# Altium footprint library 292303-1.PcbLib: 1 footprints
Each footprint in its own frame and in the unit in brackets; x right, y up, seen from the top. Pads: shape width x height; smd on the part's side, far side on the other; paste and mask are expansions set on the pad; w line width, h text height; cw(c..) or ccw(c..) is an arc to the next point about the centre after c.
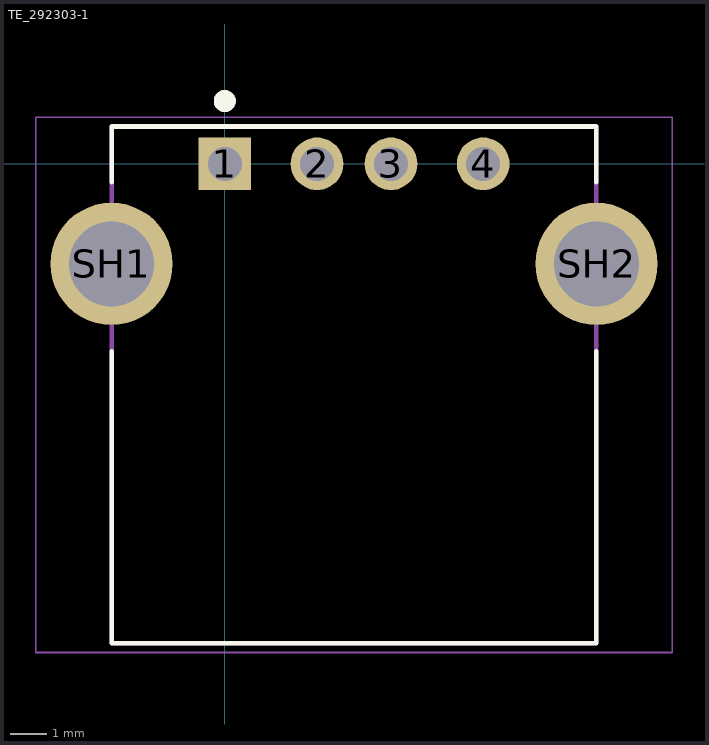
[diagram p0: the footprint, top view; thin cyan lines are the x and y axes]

## TE_292303-1 [mm]
pads (6):
  rect 1.428x1.428 hole 0.92: 1(0,0)
  round 1.428 hole 0.92: 2(2.5,0) 3(4.5,0) 4(7,0)
  round 3.316 hole 2.3: SH1(-3.07,-2.71) SH2(10.07,-2.71)
Top Overlay:
  circle w0.3: c0,1.7 r0.15
  lines w0.127: -3.065,-5.08 -3.065,-12.99 10.065,-12.99 10.065,-5.08 ; -3.065,-0.5 -3.065,1.01 10.065,1.01 10.065,-0.5
Mechanical 13:
  circle w0.3: c0,0 r0.15
  lines w0.127: -3.065,-12.99 10.065,-12.99 10.065,1.01 -3.065,1.01 -3.065,-12.99
  text "PCB EDGE" at 6.356,-15.255 h1.27
Mechanical 15:
  lines w0.05: -5.12,-13.24 12.12,-13.24 12.12,1.26 -5.12,1.26 -5.12,-13.24
3D body "292303-1.STEP": height 7.78, standoff -3.69, extent -4.444,-13.149 11.556,0.851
